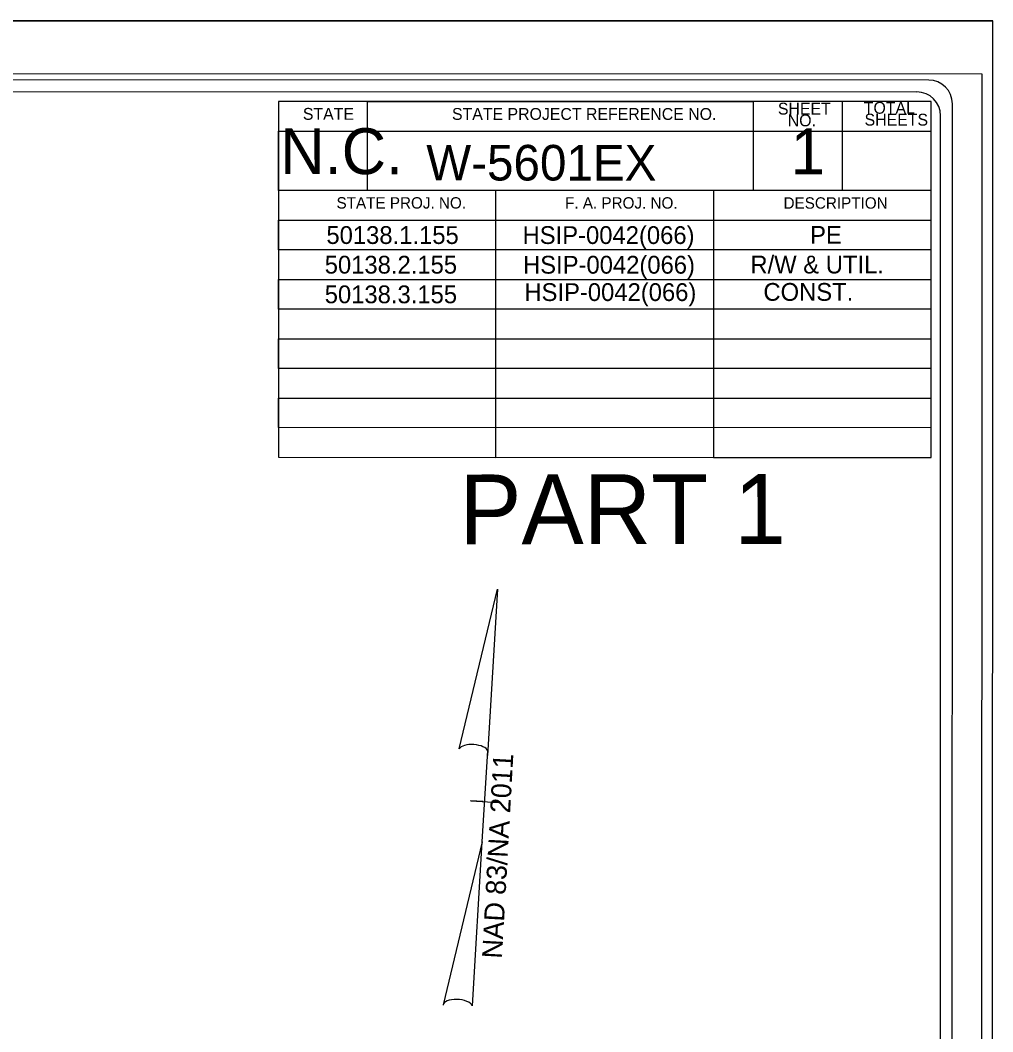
# Model space of a CAD drawing. Extents: x 2110629 to 2114002, y 669321 to 671542.
# Drawn here: x 2112822 to 2113528, y 670808 to 671542 of the extents above; entities that cross this region are included whole.
import ezdxf

# ---------------------------------------------------------------- set-up
doc = ezdxf.new("R2010")
doc.units = 0
for name, color, linetype in [('Default Symbol Cogo Number', 7, 'Continuous'), ('Exist Guardrail', 7, 'Continuous'), ('Exist Other Culture Fence Line', 7, 'Continuous'), ('Exist Roads Curbs', 7, 'Continuous'), ('Exist Roads EOP Other Text', 7, 'Continuous'), ('Exist Structure Minor Catch Basin', 7, 'Continuous'), ('Exist Utilities Telephone Test Hole SUE LOS A Text', 7, 'Continuous'), ('Exist Utilities Water Test Hole SUE LOS A Text', 7, 'Continuous')]:
    doc.layers.add(name, color=color, linetype=linetype)

msp = doc.modelspace()

# ---------------------------------------------------------------- linework, layer by layer
at = {"layer": 'Default Symbol Cogo Number'}
for p, q in [((2113140.66, 671013.49), (2113168.53, 671129.32)), ((2113168.66, 671129.32), (2113161.28, 671008.55)), ((2113168.66, 671129.32), (2113168.53, 671129.32)), ((2113168.66, 671129.32), (2113168.53, 671129.32)), ((2113157.45, 670945.89), (2113161.5, 671012.09)), ((2113161.28, 671008.55), (2113161.49, 671011.96)), ((2113149.14, 670975.82), (2113149.01, 670975.82)), ((2113158.11, 670975.27), (2113149.14, 670975.82)), ((2113149.26, 670975.81), (2113169.48, 670974.57)), ((2113157.45, 670945.89), (2113129.06, 670827.8)), ((2113150.31, 670827.01), (2113157.45, 670945.89))]:
    msp.add_line(p, q, dxfattribs=at)
for centre, start_param, end_param in [((2113151.04, 671011.6), 0.216388, 2.908219), ((2113139.74, 670826.73), 0.201328, 3.141593)]:
    msp.add_ellipse(centre, major_axis=(10.68, -0.73), ratio=0.461098, start_param=start_param, end_param=end_param, dxfattribs=at)
at = {"layer": 'Exist Roads Curbs'}
msp.add_line((2110629.24, 671542.03), (2113527.82, 671541.54), dxfattribs=at)
at = {"layer": 'Exist Roads EOP Other Text'}
msp.add_lwpolyline([(2110651.3, 669687.3), (2113519.77, 669686.81), (2113520.07, 671502.9), (2110651.61, 671503.39)], close=True, dxfattribs=at)
at = {"layer": 'Exist Structure Minor Catch Basin'}
for points in [[(2113481.37, 671498.52), (2110933.87, 671498.97)], [(2113472.74, 671489.91), (2111028.58, 671490.33)], [(2113009.67, 671224.94), (2113483.02, 671224.86), (2113483.02, 671246.36), (2113009.68, 671246.46), (2113009.68, 671267.95), (2113483.03, 671267.87), (2113483.03, 671289.39), (2113009.71, 671289.47), (2113009.69, 671311), (2113483.03, 671310.92), (2113483.04, 671332.44), (2113009.69, 671332.52), (2113009.7, 671354.01), (2113483.04, 671353.96), (2113483.04, 671375.45), (2113009.7, 671375.53), (2113009.7, 671397.05), (2113483.05, 671396.97), (2113483.05, 671418.5), (2113009.71, 671418.58), (2113009.72, 671461.61), (2113483.06, 671461.53), (2113483.06, 671483.05), (2113009.72, 671483.11), (2113009.67, 671224.94), (2113167.43, 671224.89), (2113167.46, 671418.53), (2113074.25, 671418.55), (2113074.27, 671483.12), (2113353.99, 671483.05), (2113353.96, 671418.52), (2113325.21, 671418.53), (2113325.18, 671224.89), (2113483.02, 671224.86), (2113483.06, 671483.05), (2113418.52, 671483.06), (2113418.53, 671418.51)], [(2113498.25, 669708.44), (2113498.55, 671481.3)], [(2113489.7, 670035.46), (2113489.95, 671472.72)]]:
    msp.add_lwpolyline(points, dxfattribs=at)
for centre in [(2113481.35, 671481.41), (2113472.74, 671472.8)]:
    msp.add_arc(centre, 17.21, 359.9903, 89.9903, dxfattribs=at)
at = {"layer": 'Exist Utilities Water Test Hole SUE LOS A Text'}
msp.add_lwpolyline([(2113527.82, 671541.54), (2110629.24, 671542.03), (2110628.92, 669648.68), (2113527.5, 669648.19)], close=True, dxfattribs=at)

# ---------------------------------------------------------------- texts
at = {"layer": 'Exist Guardrail'}
msp.add_text('PART 1', height=50.625, rotation=0.08379, dxfattribs=at).set_placement((2113140.83, 671161.83))
at = {"layer": 'Exist Other Culture Fence Line'}
msp.add_text('NAD 83/NA 2011', height=14.5104, rotation=86.80595, dxfattribs=at).set_placement((2113171.78, 670861.01))
at = {"layer": 'Exist Structure Minor Catch Basin'}
for s, height, p in [('STATE', 8.606, (2113027.36, 671469.79)), ('STATE PROJECT REFERENCE NO.', 8.6059, (2113135.54, 671469.75)), ('SHEET', 8.606, (2113371.95, 671473.58)), ('TOTAL', 8.606, (2113434.26, 671474.19)), ('NO.', 8.606, (2113379.1, 671465.08)), ('SHEETS', 8.606, (2113434.84, 671465.59)), ('N.C.', 33.306, (2113011, 671430.37)), ('1', 33.31, (2113381.24, 671430.31)), ('STATE PROJ. NO.', 8.262, (2113051.79, 671405.41)), ('F. A. PROJ. NO.', 8.262, (2113217.55, 671405.38)), ('DESCRIPTION', 8.262, (2113376.07, 671405.33))]:
    msp.add_text(s, height=height, rotation=359.9903, dxfattribs=at).set_placement(p)
at = {"layer": 'Exist Utilities Telephone Test Hole SUE LOS A Text'}
for s, height, p in [('W-5601EX  ', 25.819, (2113116.87, 671425.77)), ('50138.1.155', 12.9094, (2113044.44, 671379.74)), ('HSIP-0042(066)', 12.9094, (2113186.73, 671379.72)), ('PE', 12.909, (2113395.29, 671379.85)), ('50138.2.155', 12.9094, (2113043.22, 671358.23)), ('HSIP-0042(066)', 12.9094, (2113187.05, 671358.2)), ('R/W & UTIL.', 12.9094, (2113352.01, 671358.35)), ('50138.3.155', 12.9094, (2113043.22, 671336.72)), ('HSIP-0042(066)', 12.9094, (2113188.05, 671338.35)), ('CONST.     ', 12.9094, (2113361.45, 671338.49))]:
    msp.add_text(s, height=height, rotation=359.9903, dxfattribs=at).set_placement(p)

doc.saveas('drawing.dxf')
